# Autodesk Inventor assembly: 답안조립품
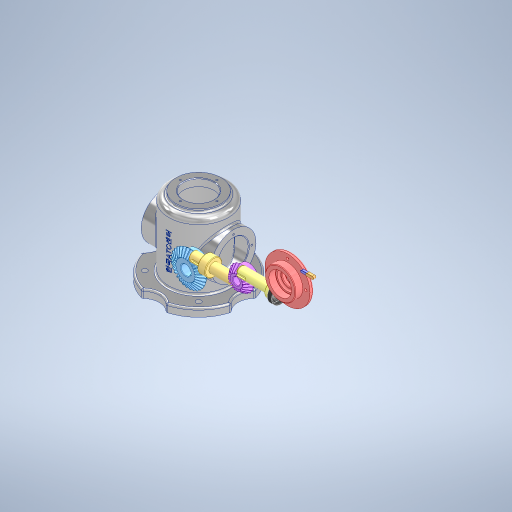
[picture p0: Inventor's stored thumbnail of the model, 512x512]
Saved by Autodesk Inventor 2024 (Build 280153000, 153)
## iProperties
Created: 2026-07
Part Number: 답안조립품
Document SubType Name: Assembly
Designer: com
Author: com
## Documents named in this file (12)
- C:\Users\com\Desktop\760703V1003\답안조립품.iam
- C:\Users\com\Desktop\760703V1003\6각 구멍붙이 볼트 M4x10\6각 구멍붙이 볼트 M4x10.ipt
- C:\Users\com\Desktop\760703V1003\깊은 홈 볼 베어링 6203\깊은 홈 볼 베어링 6203.ipt
- C:\Users\com\Desktop\760703V1003\메인 베벨기어\메인 베벨기어.ipt
- C:\Users\com\Desktop\760703V1003\메인 축\메인 축.ipt
- C:\Users\com\Desktop\760703V1003\서브 베벨기어\서브 베벨기어.ipt
- C:\Users\com\Desktop\760703V1003\서브 축\서브 축.ipt
- C:\Users\com\Desktop\760703V1003\오일 실 17 32 8\오일 실 17 32 8.ipt
- C:\Users\com\Desktop\760703V1003\커버\커버.ipt
- C:\Users\com\Desktop\760703V1003\평행 키 4x4x14\평행 키 4x4x14.ipt
- C:\Users\com\Desktop\760703V1003\평행 키 5x5x14\평행 키 5x5x14.ipt
- C:\Users\com\Desktop\760703V1003\본체.ipt
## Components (1 placed, 1 different names)
1. 6각 구멍붙이 볼트 M4x10:1
